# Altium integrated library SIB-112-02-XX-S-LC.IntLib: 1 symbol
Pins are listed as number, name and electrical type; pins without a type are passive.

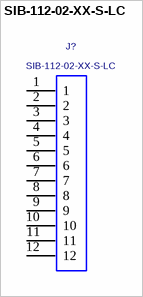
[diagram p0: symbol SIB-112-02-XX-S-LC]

## SIB-112-02-XX-S-LC
designator J?
0.100"  SINGLE INTERFACE BEAM ASSEMBLY.; MANUFACTURER: SAMTEC
footprint SIB-112-02-XX-S-LC
pins: 1, 2, 3, 4, 5, 6, 7, 8, 9, 10, 11, 12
